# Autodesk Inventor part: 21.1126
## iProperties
Created: 2006-02
Part Number: 21.1126
Material: Steel, Mild
Description: M6 ROUND WASHER DIN 125-1A
Document SubType Name: Modeling
Standard: DIN 125
Designer: Andy Moles
Standards Organization: DIN
Language: en-US
Size Designation: A 6.4
Categories: <MemberInstance><Categories><Category DisplayName="Fasteners" InternalName="e4da775c-781d-43d5-af7c-5136215cf5a6" Mnemonic="FSTN"><Category DisplayName="Washers
Density: 7.86 g/cm^3
Vendor: S
Mass: 1.01774 g
Surface Area: 2.54343 cm^2
Volume: 0.129484 cm^3
Author: Andy Moles
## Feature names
1. Body [Extrusion]
